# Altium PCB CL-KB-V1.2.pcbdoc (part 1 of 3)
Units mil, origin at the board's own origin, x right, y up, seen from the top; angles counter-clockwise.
Board outline 3269.95 x 5989.25 mil, 2 copper layers (Top Layer, Bottom Layer); 76 components, 86 nets, 398 pads, 855 vias.
Unrouted connection lines stored in the file: 1.
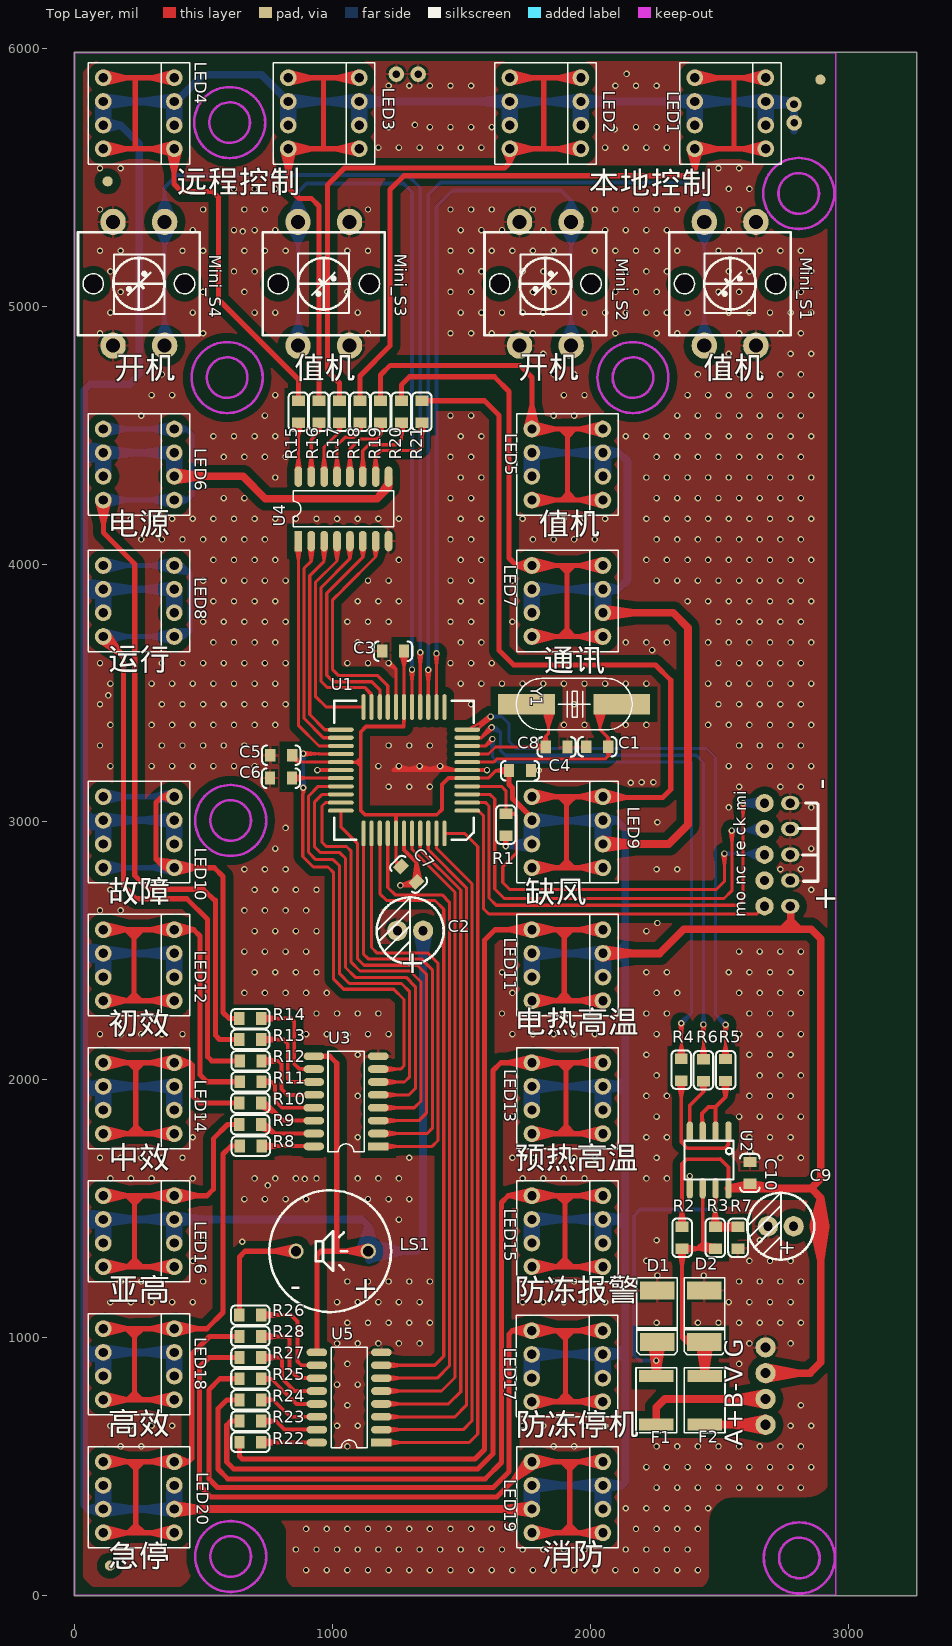
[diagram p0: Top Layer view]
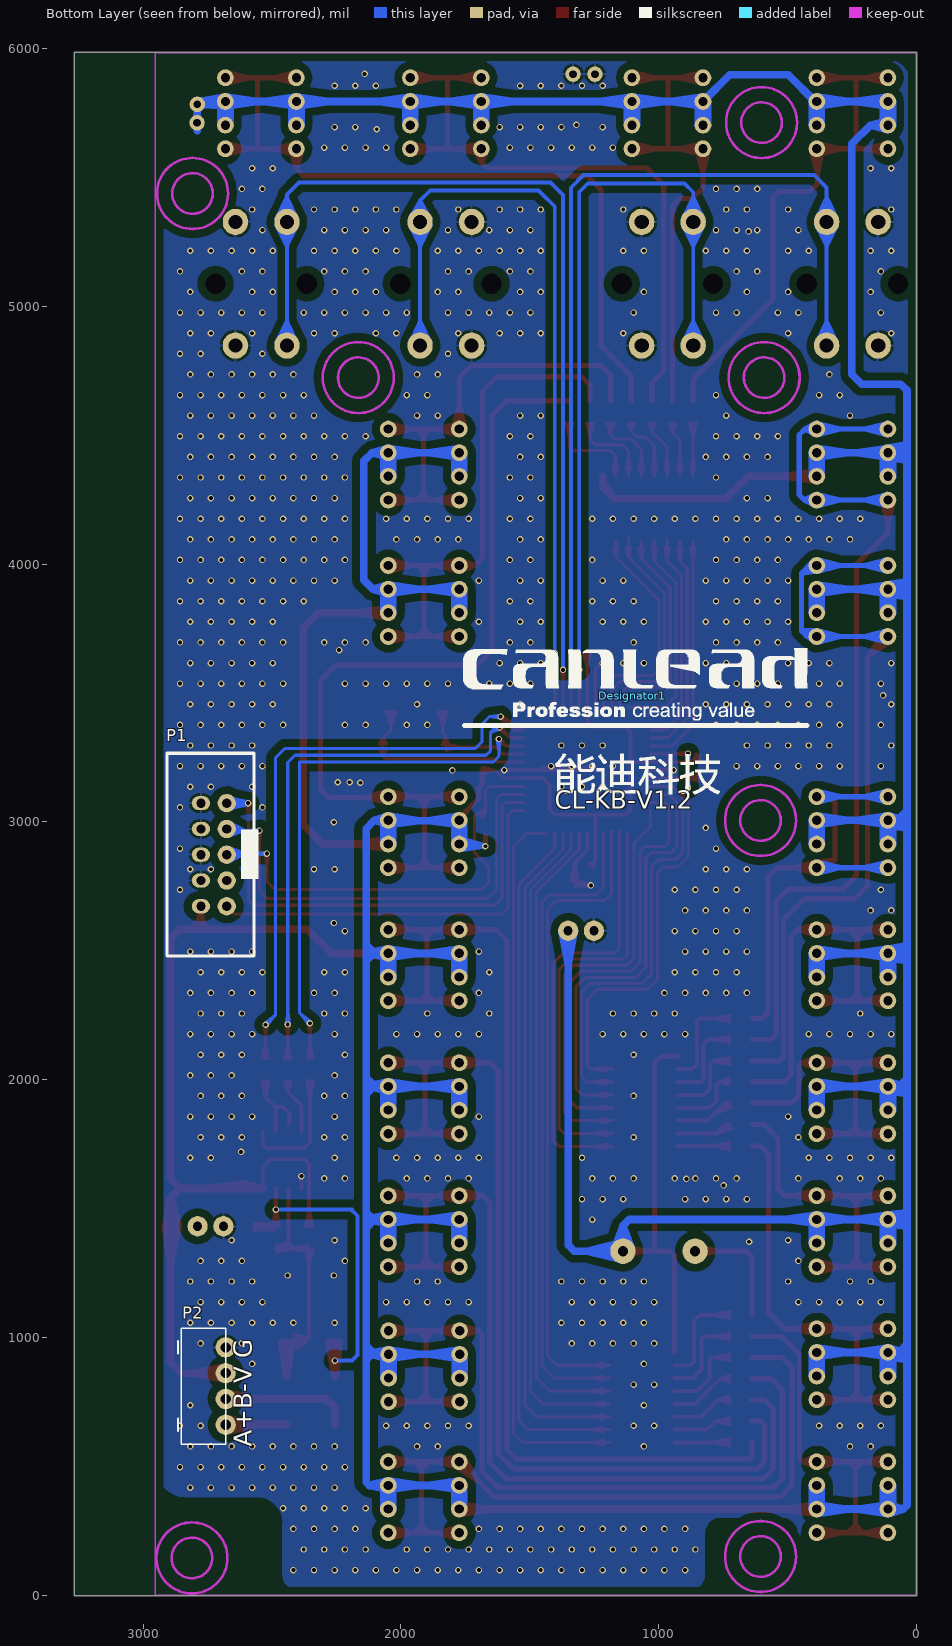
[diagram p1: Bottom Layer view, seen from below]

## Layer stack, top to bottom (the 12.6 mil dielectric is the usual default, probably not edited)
Top Solder: solder mask 0.4, Solder Resist, Dk 3.5
Top Layer: signal copper 1.4
Dielectric1: core 12.6, FR-4, Dk 4.8
Bottom Layer: signal copper 1.4
Bottom Solder: solder mask 0.4, Solder Resist, Dk 3.5

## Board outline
-2.5,-2.5 3267.45,-2.5 3267.45,5986.75 -2.5,5986.75

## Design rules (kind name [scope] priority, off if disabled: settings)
Clearance Clearance_1 [All] p1 off: gap=30
Clearance [All] p2: gap=10
ComponentClearance [All] p1 off: gap=10 collisioncheckmode=3 verticalgap=10 showdistances=FALSE
FabricationTestPointUsage TestPointUsage [All] p1 off: valid=0 allowmultiple=FALSE
FabricationTestpoint Testpoint [All] p1 off: side=3 testpointundercomponent=TRUE minsize=40 maxsize=100 preferedsize=60 minholesize=0 maxholesize=40 preferedholesize=32 testpointgrid=1 allowsidetop=TRUE allowsidebottom=TRUE usegrid=TRUE gridtolerance=0.01
Height [All] p1 off: minheight=0 maxheight=1000 prefheight=500
HoleSize [All] p1 off: absolutevalues=TRUE maxlimit=100 minlimit=1 maxpercent=80.000 minpercent=20.000
LayerPairs [All] p1 off: enforce=TRUE
PolygonConnect PolygonConnect_1 [IsVia] p1: connectstyle=Direct reliefconductorwidth=10 reliefentries=4 polygonreliefangle="90 Angle" airgapwidth=10
PolygonConnect [All] p2: connectstyle=Relief reliefconductorwidth=10 reliefentries=4 polygonreliefangle="90 Angle" airgapwidth=10
RoomDefinition aaa [InComponentClass('aaa')] p1: confinementstyle=ConfineIn formatcopy=TRUE lockcomponents=FALSE outline -17662.73,-10943.24 -15662.73,-10943.24 -15662.73,-9943.24 -17662.73,-9943.24
RoutingVias [All] p1: holewidth=28 width=50 viastyle="Through Hole" minholewidth=28 minwidth=50 maxholewidth=28 maxwidth=50
SolderMaskExpansion [All] p1: expansion=4
Width [All] p1: maxlimit=30 minlimit=10 preferedwidth=15 minimp=50.000000 maximp=50.000000 favimp=50.000000
23 further rules are at their usual default settings.

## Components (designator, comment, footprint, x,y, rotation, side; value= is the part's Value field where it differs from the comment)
C1 "22p" c0805c 2027,3292 r180 top
C2 "10uf" E6.5MM 1351,2578 r180 top
C3 "104" c0805c 1234.5,3663 r0 top
C4 "104" c0805c 1727,3199 r180 top
C5 "104" c0805c 800.5,3259 r180 top
C6 "104" c0805c 799.5,3170 r0 top
C7 "104" c0805c 1295,2797 r135 top
C8 "22p" c0805c 1869,3291 r0 top
C9 "104" c0805c 2619,1638 r90 top
C10 "220uf" E8MM 2789,1431 r180 top
D1 "SMBJ6.8" SMBJ_SMT 2259,1081.75 r270 top
D2 "SMBJ6.8" SMBJ_SMT 2442.97,1081.75 r270 top
Designator1 "Comment" ND 1103,3490 r180 bottom
F1 "X14" PPTC_SMT 2255.94,755.96 r90 top
F2 "X14" PPTC_SMT 2443.95,755.96 r90 top
LED1 "GREEN" PLED10*10 2543.28,5750 r0 top
LED2 "GREEN" PLED10*10 1825.56,5750 r0 top
LED3 "GREEN" PLED10*10 965.72,5750 r0 top
LED4 "GREEN" PLED10*10 248,5750 r0 top
LED5 "GREEN" PLED10*10 1910.99,4387.01 r0 top
LED6 "GREEN" PLED10*10 248,4387.01 r0 top
LED7 "GREEN" PLED10*10 1910.99,3857.48 r0 top
LED8 "GREEN" PLED10*10 248,3857.48 r0 top
LED9 "RED" PLED10*10 1910.99,2960.24 r0 top
LED10 "RED" PLED10*10 248,2960.24 r0 top
LED11 "RED" PLED10*10 1910.99,2444.09 r0 top
LED12 "RED" PLED10*10 248,2444.09 r0 top
LED13 "RED" PLED10*10 1910.99,1927.95 r0 top
LED14 "RED" PLED10*10 248,1927.95 r0 top
LED15 "RED" PLED10*10 1910.99,1411.81 r0 top
LED16 "RED" PLED10*10 248,1411.81 r0 top
LED17 "RED" PLED10*10 1910,888 r0 top
LED18 "RED" PLED10*10 248,895.67 r0 top
LED19 "RED" PLED10*10 1910.99,379.53 r0 top
LED20 "RED" PLED10*10 248,379.53 r0 top
LS1 "Speaker" SPK 1138,1334 r180 top
Mini_S1 "" KEYL 2542.28,5088.58 r270 top
Mini_S2 "" KEYL 1825.56,5088.58 r90 top
Mini_S3 "" KEYL 965.72,5088.58 r270 top
Mini_S4 "" KEYL 248,5088.58 r90 top
P1 "CON10" ISP 2726,2873 r270 bottom
P2 "Header 4" C3-4L 2680,811 r270 bottom
R1 "10K" 0805C 1672,3032 r270 top
R2 "3K" 0805C 2356,1429 r270 top
R3 "10K" 0805C 2485,1429 r270 top
R4 "100" 0805C 2353,1996 r90 top
R5 "100" 0805C 2525,1995 r90 top
R6 "100" 0805C 2439,1994 r90 top
R7 "3K" 0805C 2573,1344 r90 top
R8 "10K" 0805C 640,1742 r0 top
R9 "10K" 0805C 637.75,1825.54 r0 top
R10 "10K" 0805C 638,1909 r0 top
R11 "10K" 0805C 639,1992 r0 top
R12 "10K" 0805C 639,2073 r0 top
R13 "10K" 0805C 638,2156 r0 top
R14 "10K" 0805C 638,2237 r0 top
R15 "10K" 0805C 866.98,4634.52 r270 top
R16 "10K" 0805C 946.7,4634.52 r270 top
R17 "10K" 0805C 1026.43,4634.52 r270 top
R18 "10K" 0805C 1106.15,4634.52 r270 top
R19 "10K" 0805C 1185.88,4634.52 r270 top
R20 "10K" 0805C 1266.58,4634.52 r270 top
R21 "10K" 0805C 1346.31,4634.52 r270 top
R22 "10K" 0805C 638.45,593.17 r0 top
R23 "10K" 0805C 638.45,674.87 r0 top
R24 "10K" 0805C 638.45,757.55 r0 top
R25 "10K" 0805C 638.45,839.24 r0 top
R26 "3K" 0805C 723.09,1086.29 r180 top
R27 "10K" 0805C 638.45,921.92 r0 top
R28 "10K" 0805C 638.45,1003.61 r0 top
U1 "Atmega16" QFP44 1277,3201 r180 top
U2 "U485" SOP8 2461,1688 r180 top
U3 "2003" SO_16 1052,1916 r90 top
U4 "2003" SO_16 1042,4215 r0 top
U5 "2003" SO_16 1063.98,766.73 r90 top
Y1 "8M" XAL2 1937.27,3456.76 r0 top

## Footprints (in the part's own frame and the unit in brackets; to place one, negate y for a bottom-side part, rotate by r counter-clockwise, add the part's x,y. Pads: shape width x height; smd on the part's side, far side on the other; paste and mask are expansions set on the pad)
0805C [mil]
  rect 40x50 smd: 1(0,0) 2(85,0)
  silkscreen extent -32,-38 117,38
C3-4L [mm]
  round 2 hole 1: 1(-3.81,0) 2(-1.27,0) 3(1.27,0) 4(3.81,0)
  silkscreen extent -5.72,-4.7 5.71,0
c0805c [mil]
  rect 40x50 smd: 1(-42.5,0) 2(42.5,0)
  silkscreen extent -75,-38 75,38
E6.5MM [mm]
  round 2 hole 0.9: 1(0,0) 2(2.54,0)
  silkscreen extent -2.03,-3.3 4.57,3.3
E8MM [mm]
  round 2 hole 0.9: 1(0,0) 2(2.54,0)
  silkscreen extent -2.03,-3.3 4.57,3.3
ISP [mil]
  round 70.87 hole 36: 1(200,50) 3(100,50) 5(0,50) 7(-100,50) 9(-200,50)
  oval 55x70.87 hole 36: 2(200,-50) 4(100,-50) 6(0,-50) 8(-100,-50) 10(-200,-50)
  silkscreen extent -394,-181 394,173
KEYL [mil]
  round 65 hole 78.74 unplated: 0(0,177.17) 0(0,-177.17)
  oval 102x98 hole 55: 1(-240,-100) 1(240,-100) 2(-240,100) 2(240,100)
  silkscreen extent -200,-236 200,236
ND [mil]
  silkscreen extent -655,-382 679,182
PLED10*10 [mil]
  round 65 hole 36: A(-137.8,-45.93) A(-137.8,45.93) A(137.8,-45.93) A(137.8,45.93) K(-137.8,-137.8) K(-137.8,137.8) K(137.8,-137.8) K(137.8,137.8)
  silkscreen extent -197,-197 197,197
PPTC_SMT [mm]
  rect 1.2x3.4 smd: 1(-2.4,0) 2(2.4,0)
  silkscreen extent -3.2,-2 3.2,2
QFP44 [mil]
  oval 100x16 smd: 1(-245,157) 2(-245,126) 3(-245,94) 4(-245,63) 5(-245,31) 6(-245,0) 7(-245,-31) 8(-245,-63) 9(-245,-94) 10(-245,-126) 11(-245,-157) 23(245,-157) 24(245,-126) 25(245,-94) 26(245,-63) 27(245,-31) 28(245,0) 29(245,31) 30(245,63) 31(245,94) 32(245,126) 33(245,157)
  oval 16x100 smd: 12(-157,-245) 13(-126,-245) 14(-94,-245) 15(-63,-245) 16(-31,-245) 17(0,-245) 18(31,-245) 19(63,-245) 20(94,-245) 21(126,-245) 22(157,-245) 34(157,245) 35(126,245) 36(94,245) 37(63,245) 38(31,245) 39(0,245) 40(-31,245) 41(-63,245) 42(-94,245) 43(-126,245) 44(-157,245)
  silkscreen extent -270,-270 270,270
SMBJ_SMT [mil]
  rect 70x133.86 smd: A(-100,0) K(100,0)
  silkscreen extent -150,-79 149,79
SO_16 [mil]
  rect 30x80 smd: 1(-175,-125)
  oval 30x80 smd: 2(-125,-125) 3(-75,-125) 4(-25,-125) 5(25,-125) 6(75,-125) 7(125,-125) 8(175,-125) 9(175,125) 10(125,125) 11(75,125) 12(25,125) 13(-25,125) 14(-75,125) 15(-125,125) 16(-175,125)
  silkscreen extent -195,-70 195,70
SOP8 [mil]
  oval 24x80 smd: 1(-75,-110) 2(-25,-110) 3(25,-110) 4(75,-110) 5(75,110) 6(25,110) 7(-25,110) 8(-75,110)
  silkscreen extent -95,-75 95,75
SPK [mm]
  round 1.5 / inner round 1.5 / far side round 2.5 hole 1: 1(-0.007,-0.008) 2(7.105,-0.008)
  silkscreen extent -2.26,-6.01 9.74,5.99
XAL2 [mil]
  rect 220x80 smd: 1(-185,0) 2(185,0)
  silkscreen extent -225,-100 225,100

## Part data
C1 C3 C4 C5 C6 C7 C8 C9: library part Cap, "Capacitor"
C2 C10: library part "Cap Pol1", "Polarized Capacitor (Radial)"
D1 D2: library part DIODE, "Diode"
F1 F2: library part "Fuse 1", "Fuse"
LED1 LED2 LED3 LED4 LED5 LED6 LED7 LED8 LED9 LED10 LED11 LED12 LED13 LED14 LED15 LED16 LED17 LED18 LED19 LED20: library part LED, "Zener Diode"
LS1: "Loudspeaker"
Mini_S1 Mini_S2 Mini_S3 Mini_S4: library part SW-PB, "Switch"
P1: library part SPI10
P2: "Header, 4-Pin"
R1 R2 R3 R4 R5 R6 R7 R8 R9 R10 R11 R12 R13 R14 R15 R16 R17 R18 R19 R20 R21 R22 R23 R24 R25 R26 R27 R28: library part RES2
U3 U4 U5: library part ULN2003A, "High-Voltage, High-Current Darlington Array"
Y1: library part XTAL, "Crystal Oscillator"

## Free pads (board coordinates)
  round 60 hole 30: 0(1247,5902) 1(1332,5902) 3(2790,5785) 4(2791,5713)
  round 39.37 smd: 1(126.92,5486.07) 1(135.83,114.17) 1(2892.67,5880.75)
  round 86.61 on Top Solder: 2(126.92,5486.07) 2(135.83,114.17) 2(1231.25,219.34) 2(2605.27,69.73) 2(2892.67,5880.75)

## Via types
v1: diameter 25, hole 15, Top Layer to Bottom Layer, tented both sides, 855 vias

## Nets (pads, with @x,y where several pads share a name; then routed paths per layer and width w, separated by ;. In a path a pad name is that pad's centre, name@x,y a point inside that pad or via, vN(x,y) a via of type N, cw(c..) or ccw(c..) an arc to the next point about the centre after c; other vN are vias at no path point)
AREF: C6.2 U1.29 | length 346
  Top Layer w12: C6.2@842,3170 U1.29@1032,3170 ; C6.2@843.75,3156.11 898,3170 C6.2@843.75,3183.89 ; 946,3170 U1.29@990,3170
DE/RE: R5.2 U1.11 | length 3190.7
  Top Layer w12: v1@1606.51,3402.51 U1.11@1522,3358 1562,3358 v1(1613,3409) ; v1@1608.13,3413.31 1575.04,3371.04 ; v1@1609.32,3414.36 1569.32,3382.92 ; v1@1615.97,3403.22 1569.32,3382.92 ; v1@1617.31,3404.13 1575.04,3371.04 ; R5.2@2511.11,2081.75 2525,2136 R5.2@2538.89,2081.75 ; v1@2518.51,2212.56 2525,2164.5 ; R5.2@2525,2080 v1(2525,2213) 2525,2164.5 ; v1@2531.49,2212.56 2525,2164.5 ; 1569.32,3382.92 v1(1613,3409) ; 1575.04,3371.04 v1(1613,3409)
  Bottom Layer w12: v1(1613,3409) 1656,3409 ; v1@1613.49,3402.52 1656,3409 ; v1@1613.49,3415.48 1656,3409 ; v1@2520.13,2208.69 2487.04,2250.96 ; v1@2529.31,2217.87 2487.04,2250.96 ; 1656,3409 1685,3380 1685,3312 1712,3285 2451,3285 2486,3250 2486,2252 v1(2525,2213) 2487.04,2250.96
GND: C1.2 C2.2 C3.1 C4.1 C5.2 C6.1 C7.1 C8.2 C9.2 C10.2 D1.A D2.A Mini_S1.2 Mini_S2.2 Mini_S3.2 Mini_S4.2 P1.4 P1.6 P1.8 P1.10 P2.1 pad.0 pad.1@1332,5902 R7.1 U1.6 U1.18 U1.28 U1.39 U2.5 U3.8 U4.8 U5.8 | length 2285.9
  Top Layer w12: v1@1213.7,3611.32 1246,3594 ; v1(1217.27,3616.76) 1246,3594 ; v1@1220,3620 1246,3594 ; v1@1221.74,3621.48 1246,3594 ; U1.18@1246,3446 1246,3594 ; U1.18@1246,3488 1246,3532
  Top Layer w15: U1.28@990,3201 v1(941,3201) U1.28@1032,3201 ; 1273.62,3201 v1(1337.27,3216.76) 1401.56,3201 ; U1.39@1277,2914 1277,2891.5 ; U1.39@1277,2956 1277,2891.5 ; C7.1@1316.1,2770.97 1325.05,2840.23 ; C7.1@1318.24,2775.48 v1(1263,2754) ; C7.1@1321.52,2763.41 v1(1263,2754) ; 1321.8,3201 v1(1257.27,3216.76) 1235,3201 U1.6@1522,3201 v1(1599,3201) ; C7.1@1322.19,2750.93 v1(1263,2754) ; C7.1@1328.59,2770.48 1325.05,2840.23 ; C7.1@1340.96,2772.23 1325.05,2840.23 ; 1352.99,3201 v1(1417.27,3216.76) ; U1.6@1480.94,3201 v1(1417.27,3216.76) ; U1.6@1541.5,3201 v1(1599,3201) ; v1(1263,2754) 1312.1,2754 C7.1@1325.05,2766.95 1325.05,2843.45 1277,2891.5 ; v1(1417.27,3216.76) 1480,3201 1427,3201 v1(1417.27,3216.76) ; v1(1599,3201) 1564,3201 v1(1599,3201) ; v1(2386,1626) U2.5@2386,1578 v1(2386,1626) ; v1(2386,1626) 2386,1606 v1(2386,1626)
  other v1: 897.27,96.76 977.27,96.76 1057.27,96.76 1137.27,96.76 1217.27,96.76 1297.27,96.76 1377.27,96.76 1457.27,96.76 1537.27,96.76 1617.27,96.76 1697.27,96.76 1777.27,96.76 1857.27,96.76 1937.27,96.76 2017.27,96.76 2097.27,96.76 2177.27,96.76 2257.27,96.76 2337.27,96.76 2417.27,96.76 857.27,176.76 937.27,176.76 1017.27,176.76 1097.27,176.76 1177.27,176.76 1257.27,176.76 1337.27,176.76 1417.27,176.76 1497.27,176.76 1577.27,176.76 1657.27,176.76 1737.27,176.76 1817.27,176.76 1897.27,176.76 1977.27,176.76 2137.27,176.76 2217.27,176.76 2297.27,176.76 2377.27,176.76 897.27,256.76 977.27,256.76 1057.27,256.76 1137.27,256.76 1217.27,256.76 1297.27,256.76 1377.27,256.76 1457.27,256.76 1537.27,256.76 1617.27,256.76 1697.27,256.76 2177.27,256.76 2257.27,256.76 2337.27,256.76 2417.27,256.76 2137.27,336.76 2217.27,336.76 2297.27,336.76 2377.27,336.76 2457.27,336.76 2257.27,416.76 2337.27,416.76 2417.27,416.76 2497.27,416.76 2577.27,416.76 2657.27,416.76 2737.27,416.76 2817.27,416.76 2217.27,496.76 2297.27,496.76 2377.27,496.76 2457.27,496.76 2537.27,496.76 2617.27,496.76 2697.27,496.76 2777.27,496.76 2857.27,496.76 177.27,576.76 257.27,576.76 1057.27,576.76 1857.27,576.76 1937.27,576.76 2257.27,576.76 2337.27,576.76 2417.27,576.76 2497.27,576.76 2577.27,576.76 2657.27,576.76 2737.27,576.76 2817.27,576.76 137.27,656.76 217.27,656.76 297.27,656.76 377.27,656.76 1017.27,656.76 1097.27,656.76 1737.27,656.76 1817.27,656.76 1897.27,656.76 1977.27,656.76 2057.27,656.76 2777.27,656.76 2857.27,656.76 1057.27,736.76 2817.27,736.76 1017.27,816.76 1097.27,816.76 1057.27,896.76 2577.27,896.76 1017.27,976.76 1097.27,976.76 1177.27,976.76 1257.27,976.76 1337.27,976.76 2617.27,976.76 2777.27,976.76 1057.27,1056.76 1137.27,1056.76 1217.27,1056.76 1297.27,1056.76 1377.27,1056.76 2257.27,1056.76 2417.27,1056.76 2497.27,1056.76 2577.27,1056.76 2657.27,1056.76 2737.27,1056.76 2817.27,1056.76 137.27,1136.76 217.27,1136.76 297.27,1136.76 377.27,1136.76 457.27,1136.76 1017.27,1136.76 1097.27,1136.76 1177.27,1136.76 1257.27,1136.76 1337.27,1136.76 1737.27,1136.76 1817.27,1136.76 1897.27,1136.76 1977.27,1136.76 2057.27,1136.76 2537.27,1136.76 2617.27,1136.76 2697.27,1136.76 2777.27,1136.76 177.27,1216.76 257.27,1216.76 497.27,1216.76 1057.27,1216.76 1137.27,1216.76 1217.27,1216.76 1297.27,1216.76 1377.27,1216.76 1857.27,1216.76 1937.27,1216.76 2577.27,1216.76 2657.27,1216.76 2737.27,1216.76 2817.27,1216.76 2260,1240 2440,1240 457.27,1296.76 2217.27,1296.76 2617.27,1296.76 2697.27,1296.76 2777.27,1296.76 649,1371 497.27,1376.76 2257.27,1376.76 2657.27,1376.76 1257.27,1456.76 657.27,1536.76 737.27,1536.76 817.27,1536.76 897.27,1536.76 1137.27,1536.76 1217.27,1536.76 1297.27,1536.76 748,1590 892,1615 137.27,1616.76 217.27,1616.76 297.27,1616.76 457.27,1616.76 697.27,1616.76 777.27,1616.76 857.27,1616.76 937.27,1616.76 1097.27,1616.76 1177.27,1616.76 1257.27,1616.76 1737.27,1616.76 1817.27,1616.76 1897.27,1616.76 1977.27,1616.76 2217.27,1616.76 2297.27,1616.76 97.27,1696.76 177.27,1696.76 257.27,1696.76 337.27,1696.76 417.27,1696.76 1297.27,1696.76 1697.27,1696.76 1777.27,1696.76 1857.27,1696.76 1937.27,1696.76 2017.27,1696.76 2257.27,1696.76 2737.27,1696.76 2817.27,1696.76 2620,1720 457.27,1776.76 1097.27,1776.76 2217.27,1776.76 2297.27,1776.76 2617.27,1776.76 2697.27,1776.76 2777.27,1776.76 497.27,1856.76 1697.27,1856.76 2257.27,1856.76 2577.27,1856.76 2657.27,1856.76 2737.27,1856.76 2817.27,1856.76 1097.27,1936.76 2217.27,1936.76 2297.27,1936.76 2617.27,1936.76 2697.27,1936.76 2777.27,1936.76 2257.27,2016.76 2657.27,2016.76 2737.27,2016.76 2817.27,2016.76 1097.27,2096.76 2217.27,2096.76 2617.27,2096.76 2697.27,2096.76 2777.27,2096.76 97.27,2176.76 177.27,2176.76 257.27,2176.76 337.27,2176.76 417.27,2176.76 897.27,2176.76 977.27,2176.76 1057.27,2176.76 1137.27,2176.76 1217.27,2176.76 1697.27,2176.76 1777.27,2176.76 1857.27,2176.76 1937.27,2176.76 2017.27,2176.76 2257.27,2176.76 2577.27,2176.76 2657.27,2176.76 2737.27,2176.76 2817.27,2176.76 217.27,2256.76 937.27,2256.76 1017.27,2256.76 1097.27,2256.76 1177.27,2256.76 1657.27,2256.76 1897.27,2256.76 2217.27,2256.76 2297.27,2256.76 2617.27,2256.76 2697.27,2256.76 2777.27,2256.76 657.27,2336.76 737.27,2336.76 817.27,2336.76 897.27,2336.76 977.27,2336.76 1697.27,2336.76 2257.27,2336.76 2337.27,2336.76 2577.27,2336.76 2657.27,2336.76 2737.27,2336.76 2817.27,2336.76 697.27,2416.76 777.27,2416.76 857.27,2416.76 937.27,2416.76 1657.27,2416.76 2217.27,2416.76 2297.27,2416.76 2537.27,2416.76 2617.27,2416.76 2697.27,2416.76 2777.27,2416.76 657.27,2496.76 737.27,2496.76 817.27,2496.76 897.27,2496.76 1697.27,2496.76 2577.27,2496.76 2657.27,2496.76 2737.27,2496.76 2817.27,2496.76 697.27,2576.76 777.27,2576.76 857.27,2576.76 937.27,2576.76 2217.27,2576.76 2260,2608 97.27,2656.76 177.27,2656.76 657.27,2656.76 737.27,2656.76 817.27,2656.76 897.27,2656.76 137.27,2736.76 697.27,2736.76 777.27,2736.76 857.27,2736.76 937.27,2736.76 2857.27,2736.76 657.27,2816.76 737.27,2816.76 817.27,2816.76 2257.27,2816.76 2337.27,2816.76 2737.27,2816.76 2817.27,2816.76 777.27,2896.76 2857.27,2896.76 817.27,2976.76 2260,2999 2537.27,3056.76 2857.27,3056.76 1217.27,3136.76 1297.27,3136.76 1377.27,3136.76 2577.27,3136.76 2737.27,3136.76 2817.27,3136.76 2157,3152 2199,3154 2245,3154 1800,3200 137.27,3216.76 297.27,3216.76 377.27,3216.76 457.27,3216.76 537.27,3216.76 617.27,3216.76 697.27,3216.76 1177.27,3216.76 2537.27,3216.76 2617.27,3216.76 2697.27,3216.76 2777.27,3216.76 2857.27,3216.76 97.27,3296.76 337.27,3296.76 417.27,3296.76 497.27,3296.76 577.27,3296.76 657.27,3296.76 1217.27,3296.76 1297.27,3296.76 1377.27,3296.76 2577.27,3296.76 2657.27,3296.76 2737.27,3296.76 2817.27,3296.76 137.27,3376.76 297.27,3376.76 377.27,3376.76 457.27,3376.76 537.27,3376.76 617.27,3376.76 697.27,3376.76 777.27,3376.76 1897.27,3376.76 1977.27,3376.76 2137.27,3376.76 2217.27,3376.76 2457.27,3376.76 2537.27,3376.76 2617.27,3376.76 2697.27,3376.76 2777.27,3376.76 2857.27,3376.76 97.27,3456.76 337.27,3456.76 417.27,3456.76 497.27,3456.76 577.27,3456.76 657.27,3456.76 737.27,3456.76 817.27,3456.76 1537.27,3456.76 1937.27,3456.76 2497.27,3456.76 2577.27,3456.76 2657.27,3456.76 2737.27,3456.76 2817.27,3456.76 129,3491 137.27,3536.76 297.27,3536.76 377.27,3536.76 457.27,3536.76 537.27,3536.76 617.27,3536.76 697.27,3536.76 777.27,3536.76 1497.27,3536.76 1577.27,3536.76 1657.27,3536.76 1737.27,3536.76 1817.27,3536.76 1897.27,3536.76 1977.27,3536.76 2057.27,3536.76 2137.27,3536.76 2217.27,3536.76 2457.27,3536.76 2537.27,3536.76 2617.27,3536.76 2697.27,3536.76 2777.27,3536.76 2857.27,3536.76 97.27,3616.76 337.27,3616.76 417.27,3616.76 497.27,3616.76 577.27,3616.76 657.27,3616.76 737.27,3616.76 817.27,3616.76 1057.27,3616.76 1137.27,3616.76 1457.27,3616.76 1537.27,3616.76 1617.27,3616.76 2497.27,3616.76 2577.27,3616.76 2657.27,3616.76 2737.27,3616.76 2817.27,3616.76 2240,3667 537.27,3696.76 617.27,3696.76 697.27,3696.76 777.27,3696.76 1097.27,3696.76 1497.27,3696.76 1577.27,3696.76 2137.27,3696.76 2217.27,3696.76 2297.27,3696.76 2457.27,3696.76 2537.27,3696.76 2617.27,3696.76 2697.27,3696.76 2777.27,3696.76 2857.27,3696.76 497.27,3776.76 577.27,3776.76 657.27,3776.76 737.27,3776.76 817.27,3776.76 1057.27,3776.76 1137.27,3776.76 1217.27,3776.76 1457.27,3776.76 1537.27,3776.76 1697.27,3776.76 2497.27,3776.76 2577.27,3776.76 2657.27,3776.76 2737.27,3776.76 2817.27,3776.76 537.27,3856.76 617.27,3856.76 697.27,3856.76 777.27,3856.76 1097.27,3856.76 1177.27,3856.76 1257.27,3856.76 1497.27,3856.76 1577.27,3856.76 2377.27,3856.76 2457.27,3856.76 2537.27,3856.76 2617.27,3856.76 2697.27,3856.76 2777.27,3856.76 2857.27,3856.76 497.27,3936.76 577.27,3936.76 657.27,3936.76 737.27,3936.76 817.27,3936.76 1137.27,3936.76 1217.27,3936.76 1457.27,3936.76 1537.27,3936.76 1697.27,3936.76 2257.27,3936.76 2337.27,3936.76 2417.27,3936.76 2497.27,3936.76 2577.27,3936.76 2657.27,3936.76 2737.27,3936.76 2817.27,3936.76 537.27,4016.76 617.27,4016.76 697.27,4016.76 777.27,4016.76 1257.27,4016.76 1497.27,4016.76 1577.27,4016.76 2217.27,4016.76 2297.27,4016.76 2377.27,4016.76 2457.27,4016.76 2537.27,4016.76 2617.27,4016.76 2697.27,4016.76 2777.27,4016.76 2857.27,4016.76 257.27,4096.76 337.27,4096.76 417.27,4096.76 497.27,4096.76 577.27,4096.76 657.27,4096.76 737.27,4096.76 1457.27,4096.76 1537.27,4096.76 1777.27,4096.76 1857.27,4096.76 1937.27,4096.76 2017.27,4096.76 2257.27,4096.76 2337.27,4096.76 2417.27,4096.76 2497.27,4096.76 2577.27,4096.76 2657.27,4096.76 2737.27,4096.76 2817.27,4096.76 217.27,4176.76 297.27,4176.76 377.27,4176.76 457.27,4176.76 537.27,4176.76 617.27,4176.76 697.27,4176.76 777.27,4176.76 857.27,4176.76 937.27,4176.76 1017.27,4176.76 1097.27,4176.76 1177.27,4176.76 1257.27,4176.76 1497.27,4176.76 1577.27,4176.76 1737.27,4176.76 1817.27,4176.76 1897.27,4176.76 1977.27,4176.76 2057.27,4176.76 2217.27,4176.76 2297.27,4176.76 2377.27,4176.76 2457.27,4176.76 2537.27,4176.76 2617.27,4176.76 2697.27,4176.76 2777.27,4176.76 2857.27,4176.76 577.27,4256.76 657.27,4256.76 1457.27,4256.76 1537.27,4256.76 2257.27,4256.76 2337.27,4256.76 2417.27,4256.76 2497.27,4256.76 2577.27,4256.76 2657.27,4256.76 2737.27,4256.76 2817.27,4256.76 777.27,4336.76 1497.27,4336.76 1577.27,4336.76 2217.27,4336.76 2297.27,4336.76 2377.27,4336.76 2457.27,4336.76 2537.27,4336.76 2617.27,4336.76 2697.27,4336.76 2777.27,4336.76 2857.27,4336.76 577.27,4416.76 657.27,4416.76 737.27,4416.76 817.27,4416.76 1457.27,4416.76 1537.27,4416.76 2257.27,4416.76 2337.27,4416.76 2417.27,4416.76 2497.27,4416.76 2577.27,4416.76 2657.27,4416.76 2737.27,4416.76 2817.27,4416.76 537.27,4496.76 617.27,4496.76 697.27,4496.76 777.27,4496.76 1497.27,4496.76 1577.27,4496.76 2137.27,4496.76 2217.27,4496.76 2297.27,4496.76 2377.27,4496.76 2457.27,4496.76 2537.27,4496.76 2617.27,4496.76 2697.27,4496.76 2777.27,4496.76 2857.27,4496.76 257.27,4576.76 737.27,4576.76 1457.27,4576.76 1537.27,4576.76 1857.27,4576.76 1937.27,4576.76 2337.27,4576.76 2417.27,4576.76 2497.27,4576.76 2577.27,4576.76 2657.27,4576.76 2737.27,4576.76 2817.27,4576.76 297.27,4656.76 377.27,4656.76 777.27,4656.76 1897.27,4656.76 1977.27,4656.76 2377.27,4656.76 2457.27,4656.76 2537.27,4656.76 2617.27,4656.76 2697.27,4656.76 2777.27,4656.76 2857.27,4656.76 337.27,4736.76 1857.27,4736.76 1937.27,4736.76 2417.27,4736.76 2497.27,4736.76 2577.27,4736.76 2657.27,4736.76 2737.27,4736.76 2817.27,4736.76 1817.27,4816.76 2537.27,4816.76 2777.27,4816.76 2857.27,4816.76 97.27,4896.76 497.27,4896.76 1137.27,4896.76 1457.27,4896.76 1537.27,4896.76 1617.27,4896.76 1777.27,4896.76 2017.27,4896.76 2097.27,4896.76 2257.27,4896.76 2337.27,4896.76 2577.27,4896.76 2737.27,4896.76 2817.27,4896.76 137.27,4976.76 457.27,4976.76 537.27,4976.76 697.27,4976.76 777.27,4976.76 1097.27,4976.76 1497.27,4976.76 1577.27,4976.76 1657.27,4976.76 1737.27,4976.76 1817.27,4976.76 1977.27,4976.76 2057.27,4976.76 2137.27,4976.76 2217.27,4976.76 2297.27,4976.76 2377.27,4976.76 2537.27,4976.76 2617.27,4976.76 2697.27,4976.76 2777.27,4976.76 2857.27,4976.76 177.27,5056.76 497.27,5056.76 657.27,5056.76 1057.27,5056.76 1457.27,5056.76 1537.27,5056.76 1777.27,5056.76 1857.27,5056.76 2097.27,5056.76 2177.27,5056.76 2257.27,5056.76 2497.27,5056.76 2577.27,5056.76 2817.27,5056.76 137.27,5136.76 617.27,5136.76 697.27,5136.76 1497.27,5136.76 1577.27,5136.76 1737.27,5136.76 1817.27,5136.76 2137.27,5136.76 2217.27,5136.76 2297.27,5136.76 2537.27,5136.76 2617.27,5136.76 2857.27,5136.76 97.27,5216.76 177.27,5216.76 417.27,5216.76 497.27,5216.76 657.27,5216.76 737.27,5216.76 817.27,5216.76 1057.27,5216.76 1137.27,5216.76 1457.27,5216.76 1537.27,5216.76 1617.27,5216.76 1697.27,5216.76 1777.27,5216.76 1857.27,5216.76 2017.27,5216.76 2097.27,5216.76 2177.27,5216.76 2257.27,5216.76 2337.27,5216.76 2497.27,5216.76 2577.27,5216.76 2657.27,5216.76 2737.27,5216.76 2817.27,5216.76 651,5292 457.27,5296.76 617.27,5296.76 697.27,5296.76 777.27,5296.76 1497.27,5296.76 1577.27,5296.76 1657.27,5296.76 1817.27,5296.76 2057.27,5296.76 2137.27,5296.76 2217.27,5296.76 2297.27,5296.76 2537.27,5296.76 97.27,5376.76 497.27,5376.76 657.27,5376.76 737.27,5376.76 1137.27,5376.76 1457.27,5376.76 1537.27,5376.76 1617.27,5376.76 1777.27,5376.76 2017.27,5376.76 2097.27,5376.76 2177.27,5376.76 2257.27,5376.76 2337.27,5376.76 2577.27,5376.76 617.27,5456.76 697.27,5456.76 777.27,5456.76 2537.27,5456.76 2617.27,5456.76 97.27,5536.76 177.27,5536.76 2497.27,5536.76 2577.27,5536.76 1177.27,5616.76 1257.27,5616.76 1337.27,5616.76 1417.27,5616.76 1497.27,5616.76 1577.27,5616.76 2057.27,5616.76 2137.27,5616.76 2217.27,5616.76 2297.27,5616.76 2094,5688 1217.27,5696.76 1377.27,5696.76 1457.27,5696.76 1537.27,5696.76 1617.27,5696.76 2177.27,5696.76 2257.27,5696.76 1319,5705 1217.27,5856.76 1297.27,5856.76 1377.27,5856.76 1457.27,5856.76 1537.27,5856.76 2097.27,5856.76 2177.27,5856.76 2257.27,5856.76 2141,5903
IN-A+: F2.1 P2.4 | length 738
  Top Layer w30: F2.1@2443.95,661.47 2679.53,661.47 P2.4@2680,661 2550.63,661.47 ; F2.1@2487.26,661.47 2600.88,661.47 ; P2.4@2677.62,636.75 2550.63,661.47 ; P2.4@2677.79,685.27 2550.63,661.47
IN-B-: F1.1 P2.3 | length 892.3
  Top Layer w30: F1.1@2255.94,661.47 2255.94,727.94 2289,761 P2.3@2680,761 2550.63,761 ; P2.3@2677.7,736.74 2550.63,761 ; P2.3@2677.7,785.26 2550.63,761
KEY1: Mini_S1.1 U1.14 | length 5847
  Top Layer w12: v1@1364.51,3589.56 1371,3541.5 ; U1.14@1371,3446 v1(1371,3590) 1371,3541.5 ; U1.14@1371,3488 1371,3532 ; v1@1377.49,3589.56 1371,3541.5
  Bottom Layer w15: v1(1371,3590) 1371,5433 1419,5481 2396,5481 2442.28,5434.72 Mini_S1.1@2442.28,4848.58 ; Mini_S1.1@2401.8,4859.74 2442.28,4944.58 ; Mini_S1.1@2401.8,5317.42 2442.28,5232.58 ; Mini_S1.1@2401.8,5339.74 2442.28,5424.58 ; Mini_S1.1@2416.04,4854.32 2442.28,4944.58 ; Mini_S1.1@2416.04,5322.85 2442.28,5232.58 ; Mini_S1.1@2416.04,5334.32 2442.28,5424.58 ; Mini_S1.1@2430.8,4851.29 2442.28,4944.58 ; Mini_S1.1@2430.8,5325.88 2442.28,5232.58 ; Mini_S1.1@2430.8,5331.29 2442.28,5424.58 ; Mini_S1.1@2442.28,4850.58 2442.28,4944.58 ; Mini_S1.1@2442.28,5326.58 2442.28,5232.58 ; Mini_S1.1@2442.28,5330.58 2442.28,5424.58 ; Mini_S1.1@2453.75,4851.29 2442.28,4944.58 ; Mini_S1.1@2453.75,5325.88 2442.28,5232.58 ; Mini_S1.1@2453.75,5331.29 2442.28,5424.58 ; Mini_S1.1@2468.51,4854.32 2442.28,4944.58 ; Mini_S1.1@2468.51,5322.85 2442.28,5232.58 ; Mini_S1.1@2468.51,5334.32 2442.28,5424.58 ; Mini_S1.1@2482.75,4859.74 2442.28,4944.58 ; Mini_S1.1@2482.75,5317.42 2442.28,5232.58 ; Mini_S1.1@2482.75,5339.74 2442.28,5424.58
KEY2: Mini_S2.1 U1.13 | length 5141.4
  Top Layer w12: v1@1396.51,3653.56 1403,3605.5 ; U1.13@1403,3446 v1(1403,3654) 1403,3605.5 ; U1.13@1403,3488 1403,3532 ; v1@1409.49,3653.56 1403,3605.5
  Bottom Layer w15: v1(1403,3654) 1403,5388 1466,5451 1886,5451 1925.56,5411.44 ; Mini_S2.1@1885.08,4859.74 1925.56,4944.58 ; Mini_S2.1@1885.08,5317.42 1925.56,5232.58 ; Mini_S2.1@1885.45,5341.23 1925.56,5411.44 ; Mini_S2.1@1899.32,4854.32 1925.56,4944.58 ; Mini_S2.1@1899.32,5322.85 1925.56,5232.58 ; Mini_S2.1@1899.42,5334.93 1925.56,5411.44 ; Mini_S2.1@1914.08,4851.29 1925.56,4944.58 ; Mini_S2.1@1914.08,5325.88 1925.56,5232.58 ; Mini_S2.1@1914.09,5331.4 1925.56,5411.44 ; Mini_S2.1@1925.56,4848.58 1925.56,5411.44 ; Mini_S2.1@1925.56,4850.58 1925.56,4944.58 ; Mini_S2.1@1925.56,5326.58 1925.56,5232.58 ; Mini_S2.1@1925.56,5330.58 1925.56,5411.44 ; Mini_S2.1@1937.04,4851.29 1925.56,4944.58 ; Mini_S2.1@1937.04,5325.88 1925.56,5232.58 ; Mini_S2.1@1937.03,5331.4 1925.56,5411.44 ; Mini_S2.1@1951.7,5334.93 1925.56,5411.44 ; Mini_S2.1@1951.79,4854.32 1925.56,4944.58 ; Mini_S2.1@1951.79,5322.85 1925.56,5232.58 ; Mini_S2.1@1965.67,5341.23 1925.56,5411.44 ; Mini_S2.1@1966.04,4859.74 1925.56,4944.58 ; Mini_S2.1@1966.04,5317.42 1925.56,5232.58
KEY3: Mini_S3.1 U1.16 | length 5177.9
  Top Layer w12: v1@1301.51,3590.57 1308,3542.5 v1@1314.48,3590.57 ; U1.16@1308,3446 v1(1308,3591) ; U1.16@1308,3488 1308,3532
  Bottom Layer w15: Mini_S3.1@825.24,4859.74 865.72,4944.58 ; Mini_S3.1@825.24,5317.42 865.72,5232.58 ; Mini_S3.1@825.24,5339.74 865.72,5424.58 ; Mini_S3.1@839.48,4854.32 865.72,4944.58 ; Mini_S3.1@839.48,5322.85 865.72,5232.58 ; Mini_S3.1@839.48,5334.32 865.72,5424.58 ; Mini_S3.1@854.24,4851.29 865.72,4944.58 ; Mini_S3.1@854.24,5325.88 865.72,5232.58 ; Mini_S3.1@854.24,5331.29 865.72,5424.58 ; Mini_S3.1@865.72,4848.58 865.72,5443.72 899,5477 1275,5477 1308,5444 v1(1308,3591) ; Mini_S3.1@865.72,4850.58 865.72,4944.58 ; Mini_S3.1@865.72,5326.58 865.72,5232.58 ; Mini_S3.1@865.72,5330.58 865.72,5424.58 ; Mini_S3.1@877.19,4851.29 865.72,4944.58 ; Mini_S3.1@877.19,5325.88 865.72,5232.58 ; Mini_S3.1@877.19,5331.29 865.72,5424.58 ; Mini_S3.1@891.95,4854.32 865.72,4944.58 ; Mini_S3.1@891.95,5322.85 865.72,5232.58 ; Mini_S3.1@891.95,5334.32 865.72,5424.58 ; Mini_S3.1@906.19,4859.74 865.72,4944.58 ; Mini_S3.1@906.19,5317.42 865.72,5232.58 ; Mini_S3.1@906.19,5339.74 865.72,5424.58
KEY4: Mini_S4.1 U1.15 | length 5824.1
  Top Layer w12: v1@1333.51,3657.56 1340,3609.5 ; U1.15@1340,3446 v1(1340,3658) 1340,3609.5 ; U1.15@1340,3488 1340,3532 ; v1@1346.49,3657.56 1340,3609.5
  Bottom Layer w15: Mini_S4.1@307.52,4859.74 348,4944.58 ; Mini_S4.1@307.52,5317.42 348,5232.58 ; Mini_S4.1@307.52,5339.74 348,5424.58 ; Mini_S4.1@321.76,4854.32 348,4944.58 ; Mini_S4.1@321.76,5322.85 348,5232.58 ; Mini_S4.1@321.76,5334.32 348,5424.58 ; Mini_S4.1@336.52,4851.29 348,4944.58 ; Mini_S4.1@336.52,5325.88 348,5232.58 ; Mini_S4.1@336.52,5331.29 348,5424.58 ; Mini_S4.1@348,4848.58 348,5462 396,5510 1291,5510 1340,5461 v1(1340,3658) ; Mini_S4.1@348,4850.58 348,4944.58 ; Mini_S4.1@348,5326.58 348,5232.58 ; Mini_S4.1@348,5330.58 348,5424.58 ; Mini_S4.1@359.48,4851.29 348,4944.58 ; Mini_S4.1@359.48,5325.88 348,5232.58 ; Mini_S4.1@359.48,5331.29 348,5424.58 ; Mini_S4.1@374.24,4854.32 348,4944.58 ; Mini_S4.1@374.24,5322.85 348,5232.58 ; Mini_S4.1@374.24,5334.32 348,5424.58 ; Mini_S4.1@388.48,4859.74 348,4944.58 ; Mini_S4.1@388.48,5317.42 348,5232.58 ; Mini_S4.1@388.48,5339.74 348,5424.58
LAMP1: R8.2 U3.16 | length 391
  Top Layer w15: R8.2@725,1742 U3.16@926,1742 ; R8.2@726.2,1729.56 790,1742 R8.2@726.2,1754.44 ; 841.99,1742 U3.16@902,1741
LAMP2: R9.2 U3.15 | length 463.9
  Top Layer w15: R9.2@717.91,1809.02 777,1791 ; R9.2@722.75,1820.54 777,1791 ; R9.2@722.75,1825.54 742.46,1825.54 777,1791 ; R9.2@729.8,1830.86 777,1791 ; 842,1791 U3.15@902,1791 ; U3.15@927,1791 777,1791
LAMP3: R10.2 U3.14 | length 509.9
  Top Layer w15: R10.2@717.42,1892.82 784.9,1866.1 ; R10.2@723,1904 784.9,1866.1 ; R10.2@723,1909 742,1909 810,1841 U3.14@927,1841 ; R10.2@730.42,1914.06 784.9,1866.1 ; 842,1841 U3.14@902,1841
LAMP4: R11.2 U3.13 | length 418.6
  Top Layer w15: R11.2@724,1992 763,1992 ; R11.2@726,1979.66 763,1992 ; R11.2@726,2004.34 763,1992 ; 842,1891 U3.13@902,1891 ; U3.13@927,1891 803,1891 776,1918 776,1979 763,1992
LAMP5: R12.2 U3.12 | length 504.5
  Top Layer w15: R12.2@724,2073 789,2073 ; R12.2@725.2,2060.56 789,2073 ; R12.2@725.2,2085.44 789,2073 ; 842,1941 U3.12@902,1941 ; U3.12@927,1941 824,1941 801,1964 801,2061 789,2073
LAMP6: R13.2 U3.11 | length 542.6
  Top Layer w15: R13.2@723,2156 809,2156 826,2139 826,2002 837,1991 U3.11@927,1991 ; R13.2@724.2,2143.56 788,2156 R13.2@724.2,2168.44 ; 842,1991 U3.11@902,1991
LAMP7: R14.2 U3.10 | length 542.8
  Top Layer w15: R14.2@723,2237 840,2237 851,2226 851,2061 871,2041 ; R14.2@724.2,2224.56 788,2237 R14.2@724.2,2249.44 ; U3.10@902,2041 871,2041 ; U3.10@927,2041 871,2041
LAMP8: R15.2 U4.16 | length 530.5
  Top Layer w12: R15.2@853.09,4547.77 867,4493.52 ; U4.16@858.04,4365.79 867,4416 ; R15.2@866.98,4549.52 867,4493.52 ; U4.16@867,4340 R15.2@867,4549.5 ; U4.16@867,4365 867,4416 ; U4.16@875.96,4365.79 867,4416 ; R15.2@880.87,4547.78 867,4493.52
LAMP9: R16.2 U4.15 | length 485.3
  Top Layer w12: U4.15@908.04,4365.79 917,4416 ; U4.15@917,4340 917,4483 946.7,4512.7 ; U4.15@917,4365 917,4416 ; U4.15@925.96,4365.79 917,4416 ; R16.2@932.96,4546.86 946.7,4512.7 ; R16.2@960.45,4546.86 946.7,4512.7 ; 946.7,4512.7 R16.2@946.7,4549.52 946.7,4512.7
LAMP10: R17.2 U4.14 | length 492.4
  Top Layer w12: U4.14@958.04,4365.79 967,4416 ; U4.14@967,4340 967,4455 1026.43,4514.43 ; U4.14@967,4365 967,4416 ; U4.14@975.96,4365.79 967,4416 ; R17.2@1012.71,4546.73 1026.43,4514.43 ; R17.2@1040.15,4546.73 1026.43,4514.43 ; 1026.43,4514.43 R17.2@1026.43,4549.52 1026.43,4514.43
LAMP11: R18.2 U4.13 | length 515.9
  Top Layer w12: U4.13@1008.04,4365.79 1017,4416 ; U4.13@1017,4340 1017,4461 1049,4493 1082,4493 1106.15,4517.15 ; U4.13@1017,4365 1017,4416 ; U4.13@1025.96,4365.79 1017,4416 ; R18.2@1092.48,4546.49 1106.15,4517.15 ; R18.2@1119.82,4546.49 1106.15,4517.15 ; 1106.15,4517.15 R18.2@1106.15,4549.52 1106.15,4517.15
LAMP12: R19.2 U4.12 | length 595.7
  Top Layer w12: U4.12@1058.04,4365.79 1067,4416 ; U4.12@1067,4340 1067,4446.89 1106.11,4486 1171,4486 1185.88,4500.88 ; U4.12@1067,4365 1067,4416 ; U4.12@1075.96,4365.79 1067,4416 ; R19.2@1172.02,4547.51 1185.88,4500.88 ; R19.2@1199.73,4547.51 1185.88,4500.88 ; 1185.88,4500.88 R19.2@1185.88,4549.52 1185.88,4500.88
LAMP13: R20.2 U4.11 | length 654.6
  Top Layer w12: U4.11@1108.04,4365.79 1117,4416 ; U4.11@1117,4340 1117,4441 1140,4464 1246,4464 1266.58,4484.58 R20.2@1266.58,4549.52 1266.58,4493.52 ; U4.11@1117,4365 1117,4416 ; U4.11@1125.96,4365.79 1117,4416 ; R20.2@1252.69,4547.77 1266.58,4493.52 ; R20.2@1280.47,4547.77 1266.58,4493.52
LAMP14: R21.2 U4.10 | length 689.1
  Top Layer w12: U4.10@1158.04,4365.79 1167,4416 ; U4.10@1167,4340 1167,4420 1189,4442 1333,4442 1346.31,4455.31 R21.2@1346.31,4549.52 1346.31,4493.52 ; U4.10@1167,4365 1167,4416 ; U4.10@1175.96,4365.79 1167,4416 ; R21.2@1332.42,4547.77 1346.31,4493.52 ; R21.2@1360.2,4547.77 1346.31,4493.52
LAMP15: R22.2 U5.16 | length 471.3
  Top Layer w15: R22.2@724.37,580.71 788.49,591.73 ; R22.2@724.92,605.59 788.49,591.73 ; 853.98,591.73 U5.16@913.98,591.73 ; U5.16@938.98,591.73 724.89,591.73 R22.2@723.45,593.17 788.49,591.73
LAMP16: R23.2 U5.15 | length 402.1
  Top Layer w15: R23.2@723.45,674.87 779.86,674.87 ; R23.2@724.83,662.44 779.86,674.87 ; R23.2@724.83,687.29 779.86,674.87 ; 853.98,641.73 U5.15@913.98,641.73 ; U5.15@938.98,641.73 812.99,641.73 779.86,674.87
LAMP17: R24.2 U5.14 | length 394.8
  Top Layer w15: R24.2@723.45,757.55 769.45,757.55 ; R24.2@725.15,745.16 769.45,757.55 ; R24.2@725.15,769.93 769.45,757.55 ; 853.98,691.73 U5.14@913.98,691.73 ; U5.14@938.98,691.73 835.27,691.73 769.45,757.55
LAMP18: R25.2 U5.13 | length 387.3
  Top Layer w15: R25.2@723.45,839.24 761.76,839.24 ; R25.2@725.49,826.91 761.76,839.24 ; R25.2@725.49,851.57 761.76,839.24 ; U5.13@913.98,741.73 859.27,741.73 ; U5.13@938.98,741.73 859.27,741.73 ; 761.76,839.24 859.27,741.73
LAMP19: R27.2 U5.12 | length 502
  Top Layer w15: R27.2@723.45,921.92 794.08,921.92 803,913 803,840.43 851.69,791.73 U5.12@938.98,791.73 ; R27.2@724.65,909.47 788.45,921.92 R27.2@724.65,934.36 ; 853.98,791.73 U5.12@913.98,791.73
LAMP20: R28.2 U5.11 | length 529.4
  Top Layer w15: R28.2@723.45,1003.61 822.39,1003.61 833,993 833,875 866.27,841.73 ; R28.2@724.65,991.17 788.45,1003.61 R28.2@724.65,1016.05 ; U5.11@913.98,841.73 866.27,841.73 ; U5.11@938.98,841.73 866.27,841.73
LAMP21: R26.1 U5.10 | length 553.4
  Top Layer w15: R26.1@723.09,1086.29 838.71,1086.29 863,1062 863,906.72 877.98,891.73 ; R26.1@724.3,1073.84 788.09,1086.29 R26.1@724.3,1098.73 ; U5.10@913.98,891.73 877.98,891.73 ; U5.10@938.98,891.73 877.98,891.73
LEDK1: LED4.K R15.1 | length 3276.8
  Top Layer w20: LED4.K@110.2,5612.2 LED4.K@385.8,5612.2 ; LED4.K@110.2,5887.8 LED4.K@385.8,5887.8 293.3,5887.8 ; LED4.K@112.94,5589.87 202.7,5612.2 LED4.K@112.94,5634.54 ; LED4.K@112.94,5865.46 202.7,5887.8 LED4.K@112.94,5910.13 ; 234,5614.2 234,5887.8 ; LED4.K@363.41,5609.9 384,5519.67 ; LED4.K@383.06,5589.87 293.3,5612.2 ; LED4.K@383.06,5634.54 293.3,5612.2 ; LED4.K@383.06,5865.46 293.3,5887.8 ; LED4.K@383.06,5910.13 293.3,5887.8 ; LED4.K@408.07,5609.04 384,5519.67 ; R15.1@866.98,4634.52 866.98,4717.02 557,5027 557,5424 535,5446 414,5446 384,5476 384,5610.41 LED4.K@385.8,5612.2 ; 293.3,5612.2 LED4.K@385.8,5612.2 ; 384,5519.67 LED4.K@385.8,5612.2
LEDK2: LED3.K R16.1 | length 3085.7
  Top Layer w20: LED3.K@805.59,5609.47 827.92,5519.7 ; LED3.K@827.92,5887.8 LED3.K@1103.51,5887.8 1011.01,5887.8 ; LED3.K@830.66,5589.87 920.42,5612.2 LED3.K@830.66,5634.54 ; LED3.K@830.66,5865.46 920.42,5887.8 LED3.K@830.66,5910.13 ; LED3.K@850.25,5609.47 827.92,5519.7 ; R16.1@946.7,4634.52 946.7,5390.3 917,5420 868,5420 827.92,5460.08 LED3.K@827.92,5612.2 ; 964,5887.8 964,5614.2 966,5612.2 ; LED3.K@1100.78,5589.87 1011.01,5612.2 ; LED3.K@1100.78,5634.54 1011.01,5612.2 ; LED3.K@1100.78,5865.46 1011.01,5887.8 ; LED3.K@1100.78,5910.13 1011.01,5887.8 ; 827.92,5519.7 LED3.K@827.92,5612.2 ; LED3.K@827.92,5612.2 LED3.K@1103.51,5612.2 1011.01,5612.2
LEDK3: LED2.K R17.1 | length 3565
  Top Layer w20: R17.1@1026.43,4634.52 1026.43,4703.57 980,4750 980,5472 1046,5538 1667,5538 1687.76,5558.76 ; LED2.K@1665.77,5607.47 1687.76,5558.76 ; LED2.K@1687.76,5887.8 LED2.K@1963.35,5887.8 1870.85,5887.8 ; LED2.K@1690.5,5589.87 1780.26,5612.2 LED2.K@1690.5,5634.54 ; LED2.K@1690.5,5865.46 1780.26,5887.8 LED2.K@1690.5,5910.13 ; LED2.K@1709.76,5607.47 1687.76,5558.76 ; 1819,5613.2 1819,5887.8 ; LED2.K@1960.62,5589.87 1870.85,5612.2 ; LED2.K@1960.62,5634.54 1870.85,5612.2 ; LED2.K@1960.62,5865.46 1870.85,5887.8 ; LED2.K@1960.62,5910.13 1870.85,5887.8 ; 1687.76,5558.76 LED2.K@1687.76,5612.2 ; 1687.76,5558.76 LED2.K@1687.76,5612.2 ; LED2.K@1687.76,5612.2 LED2.K@1963.35,5612.2 1870.85,5612.2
